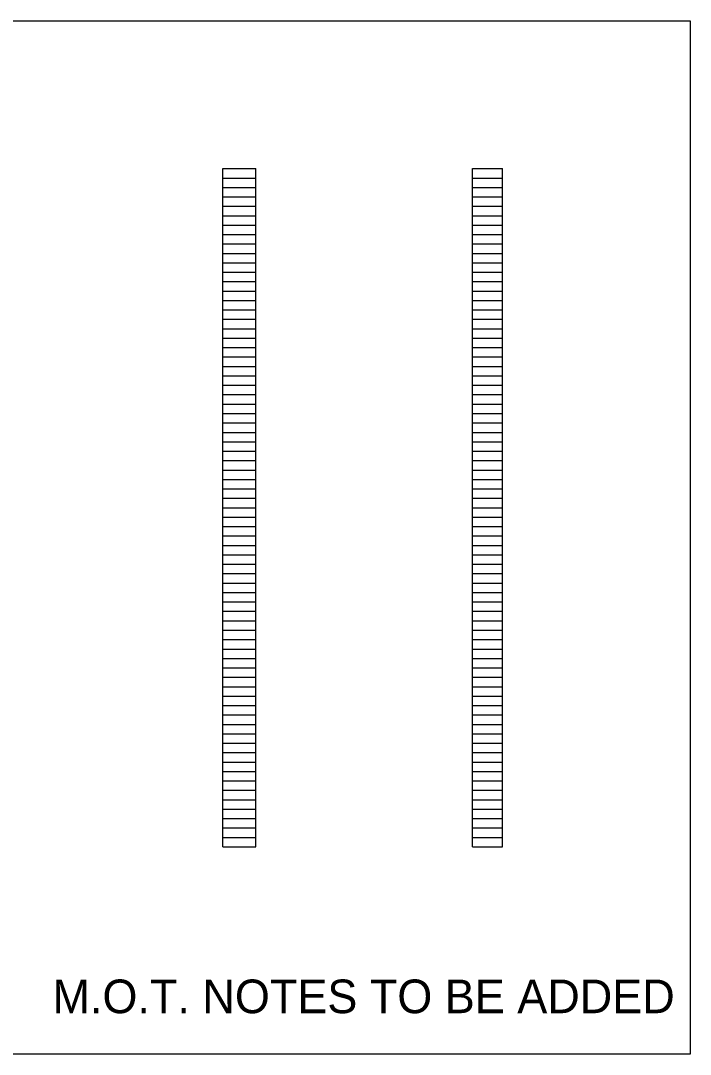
# Model space of a CAD drawing. Extents: x -49 to 78, y -12 to 34.
# Drawn here: x -25.97 to -6.06, y -7.38 to 23.35 of the extents above; entities that cross this region are included whole.
import ezdxf

# ---------------------------------------------------------------- set-up
doc = ezdxf.new("R2010")
doc.units = 0
doc.layers.add('SC_Scratch1', color=7, linetype='Continuous')
doc.layers.add('SH_Data', color=7, linetype='Continuous')

msp = doc.modelspace()

# ---------------------------------------------------------------- linework, layer by layer
at = {"layer": 'SC_Scratch1'}
msp.add_lwpolyline([(-49.098, 23.346), (-6.056, 23.346), (-6.056, -7.377), (-49.098, -7.377)], close=True, dxfattribs=at)
at = {"layer": 'SH_Data'}
for p, q in [((-19.956, -1.21), (-19.956, 18.95)), ((-19.956, 18.95), (-18.976, 18.95)), ((-18.976, -1.21), (-18.976, 18.95)), ((-12.536, -1.21), (-12.536, 18.95)), ((-12.536, 18.95), (-11.636, 18.95)), ((-11.636, -1.21), (-11.636, 18.95)), ((-19.956, 18.67), (-18.976, 18.67)), ((-12.536, 18.67), (-11.636, 18.67)), ((-19.956, 18.39), (-18.976, 18.39)), ((-12.536, 18.39), (-11.636, 18.39)), ((-19.956, 18.11), (-18.976, 18.11)), ((-19.956, 17.83), (-18.976, 17.83)), ((-12.536, 18.11), (-11.636, 18.11)), ((-12.536, 17.83), (-11.636, 17.83)), ((-19.956, 17.55), (-18.976, 17.55)), ((-12.536, 17.55), (-11.636, 17.55)), ((-19.956, 17.27), (-18.976, 17.27)), ((-12.536, 17.27), (-11.636, 17.27)), ((-19.956, 16.99), (-18.976, 16.99)), ((-12.536, 16.99), (-11.636, 16.99)), ((-19.956, 16.71), (-18.976, 16.71)), ((-12.536, 16.71), (-11.636, 16.71)), ((-19.956, 16.43), (-18.976, 16.43)), ((-12.536, 16.43), (-11.636, 16.43)), ((-19.956, 16.15), (-18.976, 16.15)), ((-12.536, 16.15), (-11.636, 16.15)), ((-19.956, 15.87), (-18.976, 15.87)), ((-12.536, 15.87), (-11.636, 15.87)), ((-19.956, 15.59), (-18.976, 15.59)), ((-12.536, 15.59), (-11.636, 15.59)), ((-19.956, 15.31), (-18.976, 15.31)), ((-12.536, 15.31), (-11.636, 15.31)), ((-19.956, 15.03), (-18.976, 15.03)), ((-19.956, 14.75), (-18.976, 14.75)), ((-12.536, 15.03), (-11.636, 15.03)), ((-12.536, 14.75), (-11.636, 14.75)), ((-19.956, 14.47), (-18.976, 14.47)), ((-12.536, 14.47), (-11.636, 14.47)), ((-19.956, 14.19), (-18.976, 14.19)), ((-12.536, 14.19), (-11.636, 14.19)), ((-19.956, 13.91), (-18.976, 13.91)), ((-12.536, 13.91), (-11.636, 13.91)), ((-19.956, 13.63), (-18.976, 13.63)), ((-12.536, 13.63), (-11.636, 13.63)), ((-19.956, 13.35), (-18.976, 13.35)), ((-12.536, 13.35), (-11.636, 13.35)), ((-19.956, 13.07), (-18.976, 13.07)), ((-12.536, 13.07), (-11.636, 13.07)), ((-19.956, 12.79), (-18.976, 12.79)), ((-12.536, 12.79), (-11.636, 12.79)), ((-19.956, 12.51), (-18.976, 12.51)), ((-12.536, 12.51), (-11.636, 12.51)), ((-19.956, 12.23), (-18.976, 12.23)), ((-12.536, 12.23), (-11.636, 12.23)), ((-19.956, 11.95), (-18.976, 11.95)), ((-12.536, 11.95), (-11.636, 11.95)), ((-19.956, 11.67), (-18.976, 11.67)), ((-19.956, 11.39), (-18.976, 11.39)), ((-12.536, 11.67), (-11.636, 11.67)), ((-12.536, 11.39), (-11.636, 11.39)), ((-19.956, 11.11), (-18.976, 11.11)), ((-12.536, 11.11), (-11.636, 11.11)), ((-19.956, 10.83), (-18.976, 10.83)), ((-12.536, 10.83), (-11.636, 10.83)), ((-19.956, 10.55), (-18.976, 10.55)), ((-12.536, 10.55), (-11.636, 10.55)), ((-19.956, 10.27), (-18.976, 10.27)), ((-12.536, 10.27), (-11.636, 10.27)), ((-19.956, 9.99), (-18.976, 9.99)), ((-12.536, 9.99), (-11.636, 9.99)), ((-19.956, 9.71), (-18.976, 9.71)), ((-12.536, 9.71), (-11.636, 9.71)), ((-19.956, 9.43), (-18.976, 9.43)), ((-12.536, 9.43), (-11.636, 9.43)), ((-19.956, 9.15), (-18.976, 9.15)), ((-12.536, 9.15), (-11.636, 9.15)), ((-19.956, 8.87), (-18.976, 8.87)), ((-12.536, 8.87), (-11.636, 8.87)), ((-19.956, 8.59), (-18.976, 8.59)), ((-19.956, 8.31), (-18.976, 8.31)), ((-12.536, 8.59), (-11.636, 8.59)), ((-12.536, 8.31), (-11.636, 8.31)), ((-19.956, 8.03), (-18.976, 8.03)), ((-12.536, 8.03), (-11.636, 8.03)), ((-19.956, 7.75), (-18.976, 7.75)), ((-12.536, 7.75), (-11.636, 7.75)), ((-19.956, 7.47), (-18.976, 7.47)), ((-12.536, 7.47), (-11.636, 7.47)), ((-19.956, 7.19), (-18.976, 7.19)), ((-12.536, 7.19), (-11.636, 7.19)), ((-19.956, 6.91), (-18.976, 6.91)), ((-12.536, 6.91), (-11.636, 6.91)), ((-19.956, 6.63), (-18.976, 6.63)), ((-12.536, 6.63), (-11.636, 6.63)), ((-19.956, 6.35), (-18.976, 6.35)), ((-12.536, 6.35), (-11.636, 6.35)), ((-19.956, 6.07), (-18.976, 6.07)), ((-12.536, 6.07), (-11.636, 6.07)), ((-19.956, 5.79), (-18.976, 5.79)), ((-12.536, 5.79), (-11.636, 5.79)), ((-19.956, 5.51), (-18.976, 5.51)), ((-19.956, 5.23), (-18.976, 5.23)), ((-12.536, 5.51), (-11.636, 5.51)), ((-12.536, 5.23), (-11.636, 5.23)), ((-19.956, 4.95), (-18.976, 4.95)), ((-12.536, 4.95), (-11.636, 4.95)), ((-19.956, 4.67), (-18.976, 4.67)), ((-12.536, 4.67), (-11.636, 4.67)), ((-19.956, 4.39), (-18.976, 4.39)), ((-12.536, 4.39), (-11.636, 4.39)), ((-19.956, 4.11), (-18.976, 4.11)), ((-12.536, 4.11), (-11.636, 4.11)), ((-19.956, 3.83), (-18.976, 3.83)), ((-12.536, 3.83), (-11.636, 3.83)), ((-19.956, 3.55), (-18.976, 3.55)), ((-12.536, 3.55), (-11.636, 3.55)), ((-19.956, 3.27), (-18.976, 3.27)), ((-12.536, 3.27), (-11.636, 3.27)), ((-19.956, 2.99), (-18.976, 2.99)), ((-12.536, 2.99), (-11.636, 2.99)), ((-19.956, 2.71), (-18.976, 2.71)), ((-12.536, 2.71), (-11.636, 2.71)), ((-19.956, 2.43), (-18.976, 2.43)), ((-12.536, 2.43), (-11.636, 2.43)), ((-19.956, 2.15), (-18.976, 2.15)), ((-19.956, 1.87), (-18.976, 1.87)), ((-12.536, 2.15), (-11.636, 2.15)), ((-12.536, 1.87), (-11.636, 1.87)), ((-19.956, 1.59), (-18.976, 1.59)), ((-12.536, 1.59), (-11.636, 1.59)), ((-19.956, 1.31), (-18.976, 1.31)), ((-12.536, 1.31), (-11.636, 1.31)), ((-19.956, 1.03), (-18.976, 1.03)), ((-12.536, 1.03), (-11.636, 1.03)), ((-19.956, 0.75), (-18.976, 0.75)), ((-12.536, 0.75), (-11.636, 0.75)), ((-19.956, 0.47), (-18.976, 0.47)), ((-12.536, 0.47), (-11.636, 0.47)), ((-19.956, 0.19), (-18.976, 0.19)), ((-12.536, 0.19), (-11.636, 0.19)), ((-19.956, -0.09), (-18.976, -0.09)), ((-12.536, -0.09), (-11.636, -0.09)), ((-19.956, -0.37), (-18.976, -0.37)), ((-12.536, -0.37), (-11.636, -0.37)), ((-19.956, -0.65), (-18.976, -0.65)), ((-12.536, -0.65), (-11.636, -0.65)), ((-19.956, -0.93), (-18.976, -0.93)), ((-19.956, -1.21), (-18.976, -1.21)), ((-12.536, -0.93), (-11.636, -0.93)), ((-12.536, -1.21), (-11.636, -1.21))]:
    msp.add_line(p, q, dxfattribs=at)

# ---------------------------------------------------------------- texts
at = {"layer": 'SC_Scratch1'}
msp.add_text('M.O.T. NOTES TO BE ADDED', height=1, dxfattribs=at).set_placement((-25.019, -6.155))

doc.saveas('drawing.dxf')
